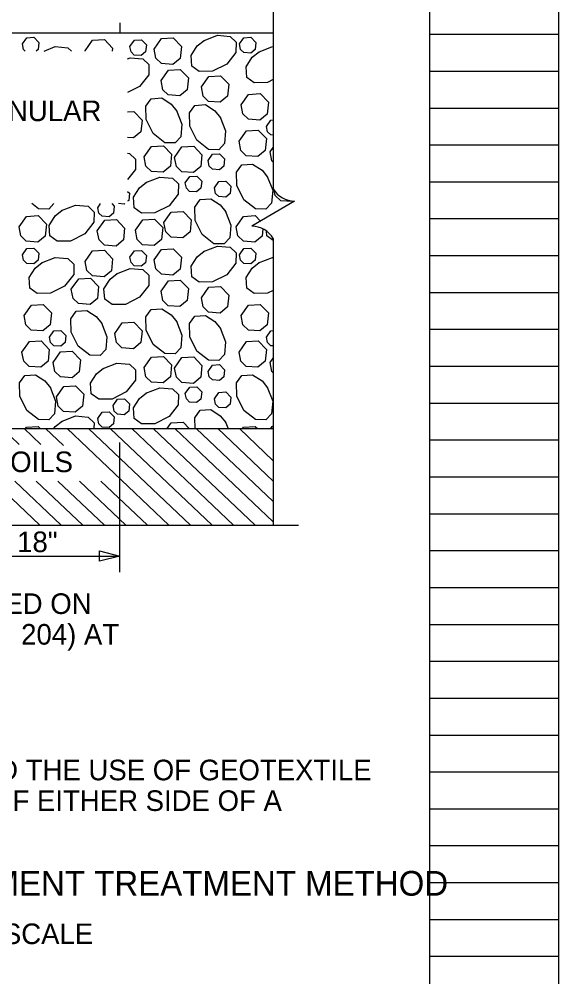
# Model space of a CAD drawing. Extents: x 0 to 34, y 0 to 22.
# Drawn here: x 6.22 to 10.32, y 10.9 to 18.17 of the extents above; entities that cross this region are included whole.
import ezdxf

# ---------------------------------------------------------------- set-up
doc = ezdxf.new("R2010")
doc.units = 0
for name, color, linetype in [('Default', 7, 'Continuous'), ('SC_Scratch1', 7, 'Continuous'), ('TX_P_1', 7, 'Continuous')]:
    doc.layers.add(name, color=color, linetype=linetype)

msp = doc.modelspace()

# ---------------------------------------------------------------- linework, layer by layer
at = {"layer": 'Default'}
for p, q in [((8.1508, 19.0284), (8.1508, 16.8858)), ((6.9864, 18.1476), (6.9864, 18.071)), ((2.8946, 18.071), (8.1508, 18.071)), ((8.3131, 16.793), (7.9885, 16.6022)), ((8.1508, 16.5094), (8.1508, 15.0088)), ((2.8946, 15.0663), (8.1508, 15.0663)), ((6.094, 15.0663), (6.2215, 14.9455)), ((6.2575, 15.0663), (6.3851, 14.9455)), ((6.4211, 15.0663), (6.5566, 14.938)), ((6.4211, 15.0663), (6.5566, 14.938)), ((6.5847, 15.0663), (7.3585, 14.3331)), ((6.7482, 15.0663), (7.5221, 14.3331)), ((6.9118, 15.0663), (7.6857, 14.3331)), ((7.0754, 15.0663), (7.8493, 14.3331)), ((7.2389, 15.0663), (8.0128, 14.3331)), ((7.4025, 15.0663), (8.1508, 14.3574)), ((7.5661, 15.0663), (8.1508, 14.5123)), ((7.7297, 15.0663), (8.1508, 14.6673)), ((7.8932, 15.0663), (8.1508, 14.8223)), ((8.1508, 15.0663), (8.1508, 14.3331)), ((6.9864, 13.9764), (6.9864, 14.9613)), ((6.0235, 14.6681), (6.3771, 14.3331)), ((6.1871, 14.6681), (6.5407, 14.3331)), ((6.3507, 14.6681), (6.7043, 14.3331)), ((6.5143, 14.6681), (6.8678, 14.3331)), ((6.6778, 14.6681), (7.0314, 14.3331)), ((6.8414, 14.6681), (7.195, 14.3331)), ((5.8908, 14.3331), (8.3429, 14.3331)), ((4.3102, 14.0989), (6.9864, 14.0989)), ((6.9864, 14.0989), (6.9522, 14.0989))]:
    msp.add_line(p, q, dxfattribs=at)
for points in [[(6.2451, 17.9861), (6.2787, 18.034), (6.3324, 18.037), (6.3697, 17.9983), (6.3643, 17.9441), (6.3506, 17.9327)], [(7.2457, 17.9471), (7.3017, 18.0268), (7.3912, 18.0319), (7.4534, 17.9674), (7.4444, 17.8771), (7.3891, 17.8311), (7.3008, 17.8375), (7.2592, 17.8778), (7.2458, 17.9471)], [(7.6217, 18.0108), (7.7265, 18.0523), (7.8227, 18.044), (7.8685, 18.0005), (7.8671, 17.9224), (7.7976, 17.8336), (7.6903, 17.78), (7.5891, 17.7782), (7.5322, 17.8187), (7.5268, 17.8992), (7.573, 17.9713), (7.6259, 18.0135)], [(7.894, 17.9861), (7.9277, 18.034), (7.9813, 18.037), (8.0186, 17.9983), (8.0132, 17.9441), (7.9801, 17.9165), (7.9271, 17.9204), (7.9022, 17.9446), (7.8941, 17.9861)], [(6.2654, 17.9327), (6.2532, 17.9446), (6.2452, 17.9861)], [(6.4104, 17.9327), (6.4951, 17.9663), (6.5914, 17.958), (6.6179, 17.9327)], [(6.7222, 17.935), (6.7782, 18.0147), (6.8677, 18.0198), (6.9299, 17.9553), (6.9276, 17.9327)], [(7.0621, 17.9678), (7.0957, 18.0155), (7.1494, 18.0186), (7.1867, 17.9799), (7.1813, 17.9258), (7.1482, 17.8982), (7.0952, 17.902), (7.0702, 17.9262), (7.0622, 17.9677)], [(8.0392, 17.9248), (8.144, 17.9663), (8.1508, 17.9657)], [(6.7227, 17.9327), (6.7222, 17.935)], [(8.1508, 17.7154), (8.1078, 17.6939), (8.0067, 17.6922), (7.9497, 17.7326), (7.9443, 17.8132), (7.9905, 17.8853), (8.0434, 17.9275)], [(7.0443, 17.8736), (7.0644, 17.8816), (7.1607, 17.8733), (7.2065, 17.8298), (7.205, 17.7516), (7.1356, 17.6629), (7.0443, 17.6172)], [(7.2984, 17.7085), (7.3544, 17.7882), (7.4439, 17.7933), (7.5061, 17.7288), (7.4971, 17.6385), (7.4418, 17.5925), (7.3535, 17.5989), (7.312, 17.6392), (7.2985, 17.7085)], [(7.6047, 17.6597), (7.6607, 17.7394), (7.7502, 17.7445), (7.8124, 17.68), (7.8034, 17.5897), (7.7481, 17.5437), (7.6598, 17.5501), (7.6183, 17.5904), (7.6048, 17.6597)], [(7.9064, 17.5242), (7.9625, 17.6039), (8.0519, 17.609), (8.1141, 17.5445), (8.1051, 17.4542), (8.0499, 17.4082), (7.9615, 17.4146), (7.92, 17.4549), (7.9065, 17.5242)], [(7.415, 17.4815), (7.4566, 17.3767), (7.4482, 17.2804), (7.4047, 17.2346), (7.3266, 17.2361), (7.2379, 17.3055), (7.1842, 17.4129), (7.1824, 17.514), (7.2229, 17.571), (7.3034, 17.5763), (7.3755, 17.5302), (7.4177, 17.4773)], [(7.7472, 17.4306), (7.7887, 17.3258), (7.7804, 17.2295), (7.7369, 17.1838), (7.6588, 17.1853), (7.57, 17.2547), (7.5164, 17.362), (7.5146, 17.4632), (7.555, 17.5201), (7.6356, 17.5255), (7.7077, 17.4793), (7.7499, 17.4264)], [(7.0443, 17.4707), (7.0917, 17.4734), (7.1539, 17.409), (7.1449, 17.3186), (7.0897, 17.2727), (7.0443, 17.2759)], [(8.0989, 17.3609), (8.1326, 17.4087), (8.1508, 17.4098)], [(7.8908, 17.2475), (7.9468, 17.3271), (8.0362, 17.3323), (8.0984, 17.2678), (8.0894, 17.1774), (8.0342, 17.1315), (7.9458, 17.1379), (7.9043, 17.1782), (7.8908, 17.2474)], [(8.1508, 17.2938), (8.132, 17.2952), (8.1071, 17.3193), (8.099, 17.3609)], [(7.1705, 17.1288), (7.2265, 17.2085), (7.3159, 17.2136), (7.3781, 17.1492), (7.3691, 17.0588), (7.3139, 17.0129), (7.2256, 17.0193), (7.184, 17.0595), (7.1705, 17.1288)], [(7.4009, 17.1254), (7.4569, 17.2051), (7.5464, 17.2103), (7.6086, 17.1458), (7.5996, 17.0554), (7.5443, 17.0095), (7.456, 17.0159), (7.4145, 17.0562), (7.401, 17.1254)], [(8.1275, 17.1683), (8.1508, 17.2015)], [(8.1508, 17.0896), (8.141, 17.099), (8.1275, 17.1683)], [(7.0443, 17.156), (7.0591, 17.1548), (7.1048, 17.1113), (7.1034, 17.0331), (7.0443, 16.9576)], [(7.6559, 17.1008), (7.6894, 17.1486), (7.7432, 17.1517), (7.7804, 17.113), (7.775, 17.0588), (7.7419, 17.0313), (7.6889, 17.0351), (7.6639, 17.0593), (7.6559, 17.1008)], [(8.1048, 16.9799), (8.1464, 16.8751), (8.138, 16.7788), (8.0945, 16.733), (8.0164, 16.7345), (7.9276, 16.804), (7.874, 16.9113), (7.8722, 17.0124), (7.9127, 17.0693), (7.9932, 17.0748), (8.0653, 17.0285), (8.1075, 16.9756)], [(7.1831, 16.9343), (7.2879, 16.9759), (7.3842, 16.9675), (7.43, 16.924), (7.4285, 16.8459), (7.3591, 16.7571), (7.2517, 16.7035), (7.1506, 16.7017), (7.0937, 16.7422), (7.0883, 16.8228), (7.1344, 16.8948), (7.1874, 16.937)], [(7.4824, 16.9327), (7.5161, 16.9805), (7.5697, 16.9836), (7.607, 16.9449), (7.6017, 16.8907), (7.5685, 16.8631), (7.5155, 16.867), (7.4906, 16.8911), (7.4825, 16.9327)], [(7.7031, 16.8933), (7.7367, 16.9411), (7.7904, 16.9442), (7.8277, 16.9055), (7.8223, 16.8513), (7.7892, 16.8237), (7.7362, 16.8275), (7.7112, 16.8517), (7.7032, 16.8933)], [(8.2998, 16.7934), (8.2958, 16.7902), (8.2075, 16.7965), (8.1659, 16.8368), (8.1588, 16.8733)], [(7.0443, 16.8672), (7.058, 16.853), (7.0526, 16.7988), (7.0443, 16.7918)], [(7.7878, 16.7155), (7.8294, 16.6107), (7.821, 16.5144), (7.7775, 16.4687), (7.6994, 16.4701), (7.6106, 16.5396), (7.557, 16.6469), (7.5552, 16.748), (7.5957, 16.805), (7.6762, 16.8104), (7.7483, 16.7642), (7.7905, 16.7113)], [(6.485, 16.7745), (6.4456, 16.733), (6.3675, 16.7345), (6.3164, 16.7745)], [(6.5427, 16.7208), (6.6475, 16.7624), (6.7437, 16.754), (6.7895, 16.7105), (6.788, 16.6324), (6.7186, 16.5437), (6.6113, 16.49), (6.5101, 16.4882), (6.4532, 16.5287), (6.4478, 16.6093), (6.494, 16.6813), (6.5469, 16.7235)], [(6.8178, 16.7435), (6.8396, 16.7745)], [(6.9244, 16.7745), (6.9424, 16.7558), (6.937, 16.7015), (6.9039, 16.674), (6.8509, 16.6778), (6.8259, 16.702), (6.8179, 16.7435)], [(7.0234, 16.7745), (7.0194, 16.7712), (6.9739, 16.7745)], [(6.2196, 16.598), (6.2756, 16.6777), (6.3651, 16.6828), (6.4272, 16.6183), (6.4182, 16.528), (6.363, 16.482), (6.2747, 16.4884), (6.2331, 16.5287), (6.2197, 16.598)], [(6.8141, 16.5684), (6.8701, 16.6481), (6.9596, 16.6532), (7.0217, 16.5888), (7.0127, 16.4984), (6.9575, 16.4524), (6.8692, 16.4588), (6.8276, 16.4991), (6.8142, 16.5684)], [(7.1031, 16.5717), (7.1592, 16.6514), (7.2486, 16.6565), (7.3108, 16.592), (7.3018, 16.5017), (7.2465, 16.4557), (7.1582, 16.4621), (7.1167, 16.5024), (7.1032, 16.5717)], [(7.3204, 16.6301), (7.3764, 16.7098), (7.4659, 16.715), (7.5281, 16.6505), (7.5191, 16.5601), (7.4638, 16.5142), (7.3755, 16.5206), (7.3339, 16.5609), (7.3204, 16.6301)], [(7.8685, 16.598), (7.9245, 16.6777), (8.014, 16.6828), (8.0543, 16.6409)], [(8.0726, 16.5824), (8.0672, 16.528), (8.0119, 16.482), (7.9236, 16.4884), (7.882, 16.5287), (7.8686, 16.598)], [(8.1508, 16.4941), (8.1021, 16.5287), (8.0996, 16.566)], [(6.2451, 16.3862), (6.2787, 16.434), (6.3324, 16.4371), (6.3697, 16.3984), (6.3643, 16.3442), (6.3312, 16.3166), (6.2782, 16.3205), (6.2532, 16.3447), (6.2452, 16.3862)], [(7.2457, 16.3472), (7.3017, 16.4269), (7.3912, 16.432), (7.4534, 16.3675), (7.4444, 16.2772), (7.3891, 16.2312), (7.3008, 16.2376), (7.2592, 16.2779), (7.2458, 16.3472)], [(7.6217, 16.4109), (7.7265, 16.4524), (7.8227, 16.4441), (7.8685, 16.4006), (7.8671, 16.3225), (7.7976, 16.2337), (7.6903, 16.18), (7.5891, 16.1783), (7.5322, 16.2188), (7.5268, 16.2993), (7.573, 16.3714), (7.6259, 16.4136)], [(7.894, 16.3862), (7.9277, 16.434), (7.9813, 16.4371), (8.0186, 16.3984), (8.0132, 16.3442), (7.9801, 16.3166), (7.9271, 16.3205), (7.9022, 16.3447), (7.8941, 16.3862)], [(6.3903, 16.3248), (6.4951, 16.3664), (6.5914, 16.3581), (6.6371, 16.3146), (6.6357, 16.2365), (6.5662, 16.1477), (6.4589, 16.094), (6.3577, 16.0923), (6.3008, 16.1327), (6.2954, 16.2133), (6.3416, 16.2853), (6.3945, 16.3275)], [(6.7222, 16.335), (6.7782, 16.4148), (6.8677, 16.4199), (6.9299, 16.3554), (6.9209, 16.265), (6.8656, 16.2191), (6.7773, 16.2255), (6.7357, 16.2658), (6.7222, 16.335)], [(7.0621, 16.3678), (7.0957, 16.4156), (7.1494, 16.4187), (7.1867, 16.38), (7.1813, 16.3258), (7.1482, 16.2983), (7.0952, 16.3021), (7.0702, 16.3263), (7.0622, 16.3678)], [(8.0392, 16.3248), (8.144, 16.3664), (8.1508, 16.3658)], [(8.1508, 16.1155), (8.1078, 16.094), (8.0067, 16.0923), (7.9497, 16.1327), (7.9443, 16.2133), (7.9905, 16.2853), (8.0434, 16.3275)], [(6.9597, 16.2401), (7.0644, 16.2817), (7.1607, 16.2733), (7.2065, 16.2298), (7.205, 16.1517), (7.1356, 16.063), (7.0282, 16.0093), (6.9271, 16.0075), (6.8702, 16.048), (6.8648, 16.1285), (6.911, 16.2006), (6.9639, 16.2428)], [(6.6168, 16.1242), (6.6728, 16.2039), (6.7622, 16.209), (6.8244, 16.1445), (6.8154, 16.0542), (6.7602, 16.0083), (6.6719, 16.0147), (6.6303, 16.055), (6.6168, 16.1242)], [(7.2984, 16.1086), (7.3544, 16.1883), (7.4439, 16.1934), (7.5061, 16.1289), (7.4971, 16.0386), (7.4418, 15.9926), (7.3535, 15.999), (7.312, 16.0393), (7.2985, 16.1086)], [(7.6047, 16.0598), (7.6607, 16.1395), (7.7502, 16.1446), (7.8124, 16.0801), (7.8034, 15.9898), (7.7481, 15.9438), (7.6598, 15.9502), (7.6183, 15.9905), (7.6048, 16.0598)], [(6.2575, 15.9243), (6.3136, 16.004), (6.403, 16.009), (6.4652, 15.9446), (6.4562, 15.8543), (6.4009, 15.8083), (6.3126, 15.8147), (6.2711, 15.855), (6.2576, 15.9243)], [(7.9064, 15.9243), (7.9625, 16.004), (8.0519, 16.009), (8.1141, 15.9446), (8.1051, 15.8543), (8.0499, 15.8083), (7.9615, 15.8147), (7.92, 15.855), (7.9065, 15.9243)], [(6.8456, 15.868), (6.8872, 15.7632), (6.8789, 15.6669), (6.8354, 15.6211), (6.7572, 15.6226), (6.6685, 15.692), (6.6148, 15.7994), (6.613, 15.9005), (6.6535, 15.9575), (6.7341, 15.9628), (6.8061, 15.9167), (6.8483, 15.8638)], [(7.415, 15.8815), (7.4566, 15.7768), (7.4482, 15.6805), (7.4047, 15.6347), (7.3266, 15.6362), (7.2379, 15.7056), (7.1842, 15.813), (7.1824, 15.9141), (7.2229, 15.971), (7.3034, 15.9764), (7.3755, 15.9303), (7.4177, 15.8773)], [(7.7472, 15.8307), (7.7887, 15.7259), (7.7804, 15.6296), (7.7369, 15.5839), (7.6588, 15.5853), (7.57, 15.6548), (7.5164, 15.7621), (7.5146, 15.8633), (7.555, 15.9202), (7.6356, 15.9256), (7.7077, 15.8794), (7.7499, 15.8265)], [(6.9463, 15.7887), (7.0023, 15.8684), (7.0917, 15.8735), (7.1539, 15.809), (7.1449, 15.7187), (7.0897, 15.6728), (7.0014, 15.6791), (6.9598, 15.7194), (6.9463, 15.7887)], [(6.45, 15.761), (6.4837, 15.8088), (6.5373, 15.8119), (6.5746, 15.7732), (6.5692, 15.719), (6.5361, 15.6914), (6.4831, 15.6953), (6.4582, 15.7194), (6.4501, 15.761)], [(8.0989, 15.761), (8.1326, 15.8088), (8.1508, 15.8098)], [(6.2419, 15.6475), (6.2979, 15.7272), (6.3873, 15.7323), (6.4495, 15.6679), (6.4405, 15.5775), (6.3852, 15.5315), (6.2969, 15.538), (6.2554, 15.5783), (6.2419, 15.6475)], [(7.8908, 15.6475), (7.9468, 15.7272), (8.0362, 15.7323), (8.0984, 15.6679), (8.0894, 15.5775), (8.0342, 15.5315), (7.9458, 15.538), (7.9043, 15.5783), (7.8908, 15.6475)], [(8.1508, 15.6939), (8.132, 15.6953), (8.1071, 15.7194), (8.099, 15.761)], [(6.4786, 15.5684), (6.5346, 15.6481), (6.624, 15.6532), (6.6862, 15.5888), (6.6772, 15.4984), (6.622, 15.4524), (6.5337, 15.4588), (6.4921, 15.4991), (6.4786, 15.5684)], [(6.858, 15.5216), (6.9628, 15.5632), (7.0591, 15.5548), (7.1048, 15.5113), (7.1034, 15.4332), (7.0339, 15.3445), (6.9266, 15.2908), (6.8254, 15.289), (6.7685, 15.3295), (6.7631, 15.41), (6.8093, 15.4821), (6.8622, 15.5243)], [(7.1705, 15.5289), (7.2265, 15.6086), (7.3159, 15.6137), (7.3781, 15.5493), (7.3691, 15.4589), (7.3139, 15.413), (7.2256, 15.4193), (7.184, 15.4596), (7.1705, 15.5289)], [(7.4009, 15.5255), (7.4569, 15.6052), (7.5464, 15.6103), (7.6086, 15.5458), (7.5996, 15.4555), (7.5443, 15.4095), (7.456, 15.416), (7.4145, 15.4563), (7.401, 15.5255)], [(8.1275, 15.5684), (8.1508, 15.6016)], [(8.1508, 15.4896), (8.141, 15.4991), (8.1275, 15.5684)], [(7.6559, 15.5009), (7.6894, 15.5487), (7.7432, 15.5518), (7.7804, 15.5131), (7.775, 15.4589), (7.7419, 15.4313), (7.6889, 15.4352), (7.6639, 15.4593), (7.6559, 15.5009)], [(6.4559, 15.38), (6.4974, 15.2752), (6.4891, 15.1789), (6.4456, 15.1331), (6.3675, 15.1346), (6.2787, 15.204), (6.2251, 15.3113), (6.2233, 15.4125), (6.2637, 15.4694), (6.3443, 15.4748), (6.4164, 15.4286), (6.4586, 15.3757)], [(8.1048, 15.38), (8.1464, 15.2752), (8.138, 15.1789), (8.0945, 15.1331), (8.0164, 15.1346), (7.9276, 15.204), (7.874, 15.3113), (7.8722, 15.4125), (7.9127, 15.4694), (7.9932, 15.4748), (8.0653, 15.4286), (8.1075, 15.3757)], [(6.5035, 15.3062), (6.5595, 15.3859), (6.649, 15.391), (6.7112, 15.3265), (6.7022, 15.2362), (6.6469, 15.1903), (6.5586, 15.1966), (6.517, 15.2369), (6.5035, 15.3062)], [(7.1831, 15.3344), (7.2879, 15.376), (7.3842, 15.3676), (7.43, 15.3241), (7.4285, 15.246), (7.3591, 15.1572), (7.2517, 15.1036), (7.1506, 15.1018), (7.0937, 15.1423), (7.0883, 15.2228), (7.1344, 15.2949), (7.1874, 15.3371)], [(7.4824, 15.3328), (7.5161, 15.3806), (7.5697, 15.3837), (7.607, 15.345), (7.6017, 15.2908), (7.5685, 15.2632), (7.5155, 15.267), (7.4906, 15.2912), (7.4825, 15.3328)], [(7.7031, 15.2934), (7.7367, 15.3412), (7.7904, 15.3443), (7.8277, 15.3055), (7.8223, 15.2514), (7.7892, 15.2238), (7.7362, 15.2276), (7.7112, 15.2518), (7.7032, 15.2933)], [(6.9334, 15.2408), (6.967, 15.2887), (7.0207, 15.2917), (7.058, 15.253), (7.0526, 15.1988), (7.0194, 15.1713), (6.9664, 15.1751), (6.9415, 15.1993), (6.9334, 15.2408)], [(7.5566, 15.0663), (7.5552, 15.1481), (7.5957, 15.2051), (7.6762, 15.2105), (7.7483, 15.1643), (7.7905, 15.1114)], [(6.4843, 15.0663), (6.494, 15.0814), (6.5469, 15.1236)], [(6.5427, 15.1209), (6.6475, 15.1625), (6.7437, 15.1541), (6.7895, 15.1106), (6.7887, 15.0663)], [(6.8178, 15.1436), (6.8514, 15.1915), (6.9051, 15.1945), (6.9424, 15.1558), (6.937, 15.1016), (6.9039, 15.074), (6.8509, 15.0779), (6.8259, 15.102), (6.8179, 15.1436)], [(6.2676, 15.0663), (6.2756, 15.0778), (6.3651, 15.0828), (6.381, 15.0663)], [(7.3458, 15.0663), (7.3764, 15.1099), (7.4659, 15.115), (7.5128, 15.0663)], [(7.7878, 15.1156), (7.8073, 15.0663)], [(7.9165, 15.0663), (7.9245, 15.0778), (8.014, 15.0828), (8.0299, 15.0663)], [(8.1333, 15.0663), (8.1429, 15.0814), (8.1508, 15.0877)]]:
    msp.add_lwpolyline(points, dxfattribs=at)
msp.add_lwpolyline([(6.8304, 14.1379), (6.9864, 14.0989), (6.8304, 14.0599)], close=True, dxfattribs=at)
for centre, start, end in [((8.3131, 16.9812), 210.44223, 269.99999), ((7.9885, 16.414), 30.44222, 89.99999)]:
    msp.add_arc(centre, 0.1882, start, end, dxfattribs=at)
at = {"layer": 'SC_Scratch1'}
for p, q in [((9.34, 0.98), (9.34, 21.14)), ((10.32, 0.98), (10.32, 21.14)), ((9.34, 18.06), (10.32, 18.06)), ((9.34, 17.78), (10.32, 17.78)), ((9.34, 17.5), (10.32, 17.5)), ((9.34, 17.22), (10.32, 17.22)), ((9.34, 16.94), (10.32, 16.94)), ((9.34, 16.66), (10.32, 16.66)), ((9.34, 16.38), (10.32, 16.38)), ((9.34, 16.1), (10.32, 16.1)), ((9.34, 15.82), (10.32, 15.82)), ((9.34, 15.54), (10.32, 15.54)), ((9.34, 15.26), (10.32, 15.26)), ((9.34, 14.98), (10.32, 14.98)), ((9.34, 14.7), (10.32, 14.7)), ((9.34, 14.42), (10.32, 14.42)), ((9.34, 14.14), (10.32, 14.14)), ((9.34, 13.86), (10.32, 13.86)), ((9.34, 13.58), (10.32, 13.58)), ((9.34, 13.3), (10.32, 13.3)), ((9.34, 13.02), (10.32, 13.02)), ((9.34, 12.74), (10.32, 12.74)), ((9.34, 12.46), (10.32, 12.46)), ((9.34, 12.18), (10.32, 12.18)), ((9.34, 11.9), (10.32, 11.9)), ((9.34, 11.62), (10.32, 11.62)), ((9.34, 11.34), (10.32, 11.34)), ((9.34, 11.06), (10.32, 11.06))]:
    msp.add_line(p, q, dxfattribs=at)

# ---------------------------------------------------------------- texts
at = {"layer": 'Default'}
for s, height, p in [('703.16 GRANULAR', 0.156486, (4.9841, 17.4005)), ('SOILS', 0.15649, (6.0129, 14.7356)), ('18"', 0.15649, (6.2054, 14.1285)), ('GEOGRID (ITEM 204) PLACED ON ', 0.156486, (3.4104, 13.659)), ('GEOTEXTILE FABRIC (ITEM 204) AT ', 0.156486, (3.4104, 13.4262)), ('THE CONTRACTOR SHALL SUSPEND THE USE OF GEOTEXTILE ', 0.156486, (2.4681, 12.3962)), ('FABRIC AND GEOGRID WITHIN 18" OF EITHER SIDE OF A ', 0.156486, (2.4681, 12.1634)), ('NOT TO SCALE', 0.156486, (5.2484, 11.1525))]:
    msp.add_text(s, height=height, rotation=359.99999, dxfattribs=at).set_placement(p)
at = {"layer": 'TX_P_1'}
msp.add_text('DETAIL - UNDERCUT/ REPLACEMENT TREATMENT METHOD', height=0.1875, rotation=359.99999, dxfattribs=at).set_placement((2.1935, 11.5202))

doc.saveas('drawing.dxf')
